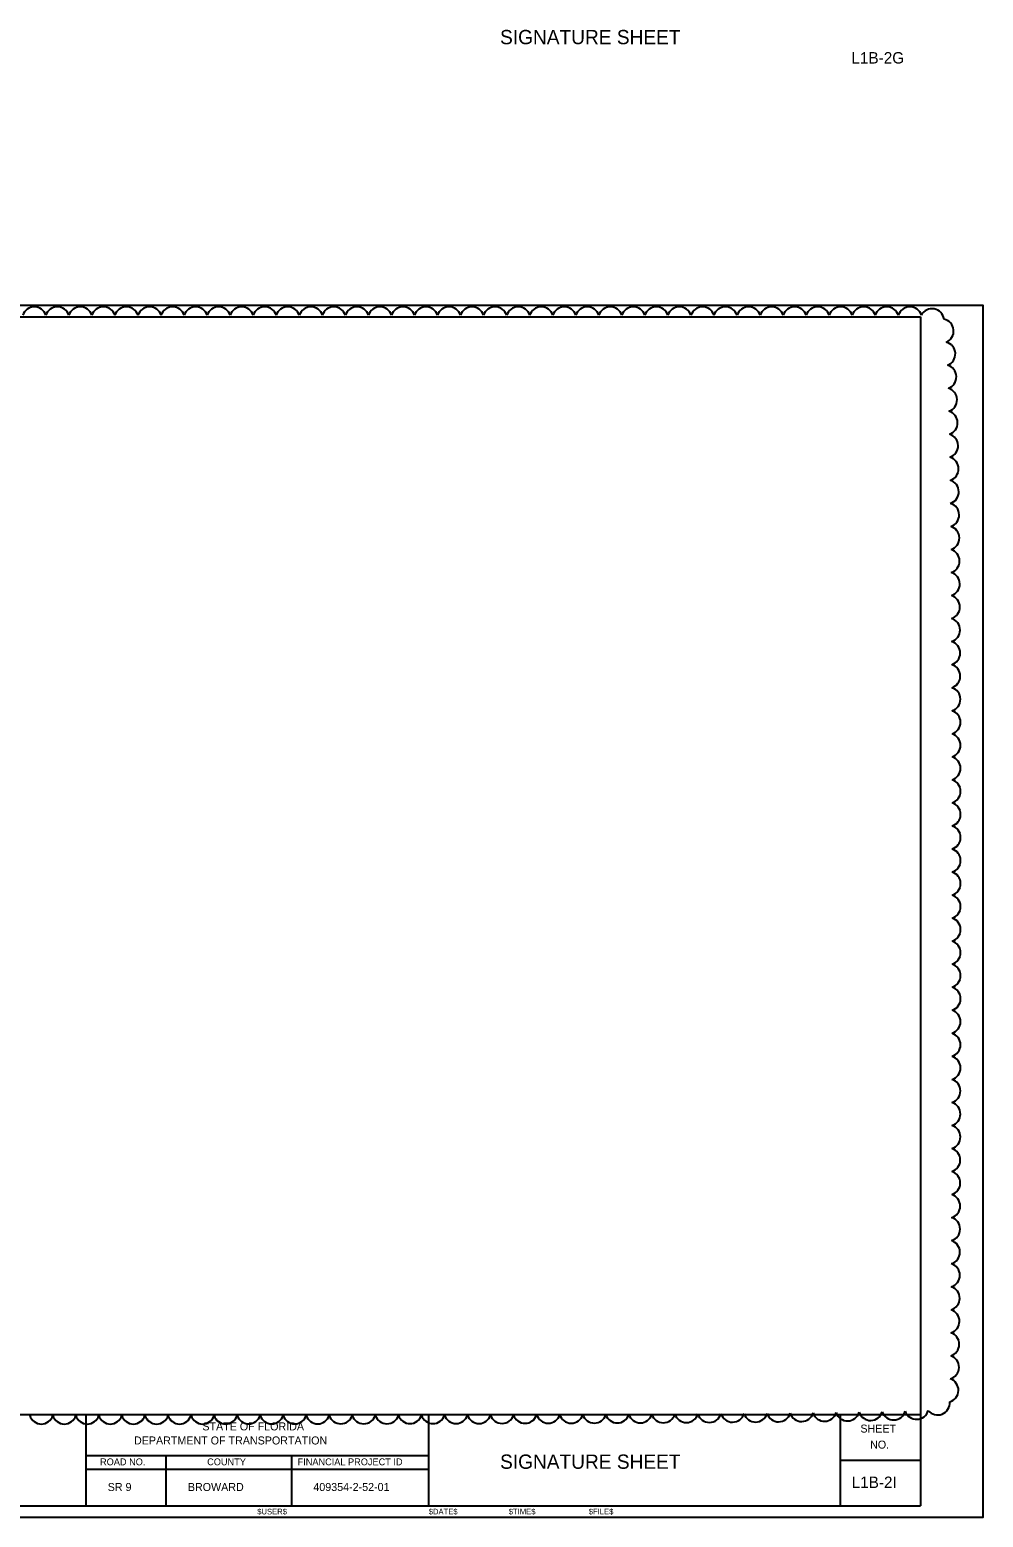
# Model space of a CAD drawing. Extents: x -811.2 to -755.6, y -2295.2 to -2235.1.
# Drawn here: x -775.75 to -767.41, y -2282.95 to -2269.93 of the extents above; entities that cross this region are included whole.
import ezdxf

# ---------------------------------------------------------------- set-up
doc = ezdxf.new("R2010")
doc.units = 0
for name, color, linetype in [('Cloud_dp', 7, 'Continuous'), ('PlotBorder_dp', 7, 'Continuous'), ('SheetBorder_dp', 7, 'Continuous'), ('SheetLines_dp', 7, 'Continuous'), ('TextMinor', 7, 'Continuous'), ('TextMisc', 7, 'Continuous'), ('TextShtNo', 7, 'Continuous')]:
    doc.layers.add(name, color=color, linetype=linetype)

msp = doc.modelspace()

# ---------------------------------------------------------------- linework, layer by layer
at = {"layer": 'Cloud_dp'}
for centre, start, end in [((-775.707, -2272.463), 17.5, 162.5), ((-775.505, -2272.463), 17.5, 162.5), ((-775.304, -2272.463), 17.5, 162.5), ((-775.102, -2272.463), 17.5, 162.5), ((-774.901, -2272.463), 17.5, 162.5), ((-774.699, -2272.463), 17.5, 162.5), ((-774.498, -2272.463), 17.5, 162.5), ((-774.296, -2272.463), 17.5, 162.5), ((-774.095, -2272.463), 17.5, 162.5), ((-773.893, -2272.463), 17.5, 162.5), ((-773.691, -2272.463), 17.5, 162.5), ((-773.49, -2272.463), 17.5, 162.5), ((-773.288, -2272.463), 17.5, 162.5), ((-773.087, -2272.463), 17.5, 162.5), ((-772.885, -2272.463), 17.5, 162.5), ((-772.684, -2272.463), 17.5, 162.5), ((-772.482, -2272.463), 17.5, 162.5), ((-772.281, -2272.463), 17.5, 162.5), ((-772.079, -2272.463), 17.5, 162.5), ((-771.878, -2272.463), 17.5, 162.5), ((-771.676, -2272.463), 17.5, 162.5), ((-771.474, -2272.463), 17.5, 162.5), ((-771.273, -2272.463), 17.5, 162.5), ((-771.071, -2272.463), 17.5, 162.5), ((-770.87, -2272.463), 17.5, 162.5), ((-770.668, -2272.463), 17.5, 162.5), ((-770.467, -2272.463), 17.5, 162.5), ((-770.265, -2272.463), 17.5, 162.5), ((-770.064, -2272.463), 17.5, 162.5), ((-769.862, -2272.463), 17.5, 162.5), ((-769.661, -2272.463), 17.5, 162.5), ((-769.459, -2272.463), 17.5, 162.5), ((-769.257, -2272.463), 17.5, 162.5), ((-769.056, -2272.463), 17.5, 162.5), ((-768.854, -2272.463), 17.5, 162.5), ((-768.653, -2272.463), 17.5, 162.5), ((-768.451, -2272.463), 17.5, 162.5), ((-768.25, -2272.463), 17.5, 162.5), ((-768.048, -2272.463), 17.5, 162.5), ((-767.854, -2272.48), 7.7061, 152.7061), ((-767.771, -2272.569), 293.1451, 78.1451), ((-767.756, -2272.769), 290.3535, 75.3535), ((-767.747, -2272.97), 289.5186, 74.5186), ((-767.741, -2273.171), 289.0656, 74.0656), ((-767.736, -2273.372), 288.7699, 73.7699), ((-767.732, -2273.573), 288.5573, 73.5573), ((-767.728, -2273.775), 288.3949, 73.3949), ((-767.726, -2273.976), 288.2656, 73.2656), ((-767.723, -2274.178), 288.1595, 73.1595), ((-767.721, -2274.379), 288.0704, 73.0704), ((-767.719, -2274.581), 287.9942, 72.9942), ((-767.717, -2274.782), 287.928, 72.928), ((-767.716, -2274.984), 287.8698, 72.8698), ((-767.715, -2275.185), 287.8182, 72.8182), ((-767.714, -2275.387), 287.772, 72.772), ((-767.713, -2275.588), 287.7302, 72.7302), ((-767.712, -2275.79), 287.6923, 72.6923), ((-767.711, -2275.991), 287.6577, 72.6577), ((-767.711, -2276.193), 287.6259, 72.6259), ((-767.711, -2276.394), 287.5965, 72.5965), ((-767.71, -2276.596), 287.5693, 72.5693), ((-767.71, -2276.798), 287.544, 72.544), ((-767.71, -2276.999), 287.5204, 72.5204), ((-767.71, -2277.201), 287.5008, 72.5008), ((-767.71, -2277.402), 287.4924, 72.4924), ((-767.71, -2277.604), 287.4849, 72.4849), ((-767.71, -2277.805), 287.4769, 72.4769), ((-767.71, -2278.007), 287.4682, 72.4682), ((-767.71, -2278.208), 287.4589, 72.4589), ((-767.71, -2278.41), 287.4488, 72.4488), ((-767.711, -2278.611), 287.4378, 72.4378), ((-767.711, -2278.813), 287.4258, 72.4258), ((-767.711, -2279.015), 287.4126, 72.4126), ((-767.712, -2279.216), 287.398, 72.398), ((-767.712, -2279.418), 287.3817, 72.3817), ((-767.712, -2279.619), 287.3633, 72.3633), ((-767.713, -2279.821), 287.3425, 72.3425), ((-767.713, -2280.022), 287.3185, 72.3185), ((-767.714, -2280.224), 287.2905, 72.2905), ((-767.715, -2280.425), 287.2573, 72.2573), ((-767.716, -2280.627), 287.217, 72.217), ((-767.717, -2280.828), 287.1666, 72.1666), ((-767.718, -2281.03), 287.101, 72.101), ((-767.72, -2281.231), 287.0106, 72.0106), ((-767.722, -2281.433), 286.8744, 71.8744), ((-767.724, -2281.634), 286.6317, 71.6317), ((-767.729, -2281.835), 285.9387, 70.9387), ((-767.805, -2281.945), 219.2472, 4.2472), ((-775.646, -2282.024), 197.4989, 342.4989), ((-775.445, -2282.024), 197.5044, 342.5044), ((-775.243, -2282.024), 197.5105, 342.5105), ((-775.042, -2282.024), 197.5167, 342.5167), ((-774.84, -2282.024), 197.5233, 342.5233), ((-774.638, -2282.024), 197.5301, 342.5301), ((-774.437, -2282.024), 197.5372, 342.5372), ((-774.235, -2282.024), 197.5447, 342.5447), ((-774.034, -2282.024), 197.5525, 342.5525), ((-773.832, -2282.023), 197.5607, 342.5607), ((-773.631, -2282.023), 197.5693, 342.5693), ((-773.429, -2282.023), 197.5784, 342.5784), ((-773.228, -2282.023), 197.5879, 342.5879), ((-773.026, -2282.022), 197.598, 342.598), ((-772.825, -2282.022), 197.6087, 342.6087), ((-772.623, -2282.022), 197.62, 342.62), ((-772.421, -2282.021), 197.6321, 342.6321), ((-772.22, -2282.021), 197.6449, 342.6449), ((-772.018, -2282.02), 197.6587, 342.6587), ((-771.817, -2282.02), 197.6734, 342.6734), ((-771.615, -2282.019), 197.6893, 342.6893), ((-771.414, -2282.018), 197.7064, 342.7064), ((-771.212, -2282.017), 197.725, 342.725), ((-771.011, -2282.017), 197.7453, 342.7453), ((-770.809, -2282.016), 197.7675, 342.7675), ((-770.608, -2282.015), 197.792, 342.792), ((-770.406, -2282.014), 197.8192, 342.8192), ((-770.205, -2282.013), 197.8496, 342.8496), ((-770.003, -2282.011), 197.8839, 342.8839), ((-769.802, -2282.01), 197.9231, 342.9231), ((-769.6, -2282.008), 197.9684, 342.9684), ((-769.398, -2282.007), 198.0216, 343.0216), ((-769.197, -2282.005), 198.0853, 343.0853), ((-768.995, -2282.002), 198.1633, 343.1633), ((-768.794, -2282), 198.2623, 343.2623), ((-768.593, -2281.997), 198.3936, 343.3936), ((-768.391, -2281.993), 198.5799, 343.5799), ((-768.19, -2281.989), 198.8753, 343.8753), ((-767.989, -2281.983), 199.4643, 344.4643)]:
    msp.add_arc(centre, 0.106, start, end, dxfattribs=at)
at = {"layer": 'PlotBorder_dp'}
msp.add_lwpolyline([(-783.906, -2282.946), (-767.406, -2282.946), (-767.406, -2272.346), (-783.906, -2272.346)], close=True, dxfattribs=at)
at = {"layer": 'SheetBorder_dp'}
for p, q in [((-783.356, -2272.446), (-767.956, -2272.446)), ((-767.956, -2272.446), (-767.956, -2282.846)), ((-783.356, -2282.046), (-767.956, -2282.046)), ((-783.356, -2282.846), (-767.956, -2282.846))]:
    msp.add_line(p, q, dxfattribs=at)
at = {"layer": 'SheetLines_dp'}
for p, q in [((-775.256, -2282.046), (-775.256, -2282.846)), ((-772.256, -2282.846), (-772.256, -2282.046)), ((-768.656, -2282.846), (-768.656, -2282.046)), ((-775.256, -2282.406), (-772.256, -2282.406)), ((-774.556, -2282.406), (-774.556, -2282.846)), ((-773.456, -2282.406), (-773.456, -2282.846)), ((-768.656, -2282.446), (-767.956, -2282.446)), ((-775.256, -2282.526), (-772.256, -2282.526))]:
    msp.add_line(p, q, dxfattribs=at)

# ---------------------------------------------------------------- texts
at = {"layer": 'TextMinor'}
msp.add_text('$USER$', height=0.05, dxfattribs=at).set_placement((-773.757, -2282.921))
for s, p in [('$DATE$', (-772.257, -2282.921)), ('$TIME$', (-771.557, -2282.921)), ('$FILE$', (-770.857, -2282.921))]:
    msp.add_text(s, height=0.05, rotation=360, dxfattribs=at).set_placement(p)
at = {"layer": 'TextMisc'}
for s, height, p in [('       SIGNATURE SHEET         ', 0.125, (-771.958, -2270.06)), ('STATE OF FLORIDA', 0.07, (-774.237, -2282.186)), ('DEPARTMENT OF TRANSPORTATION', 0.07, (-774.835, -2282.309)), ('ROAD NO.', 0.06, (-775.132, -2282.491)), ('COUNTY', 0.06, (-774.195, -2282.491)), ('FINANCIAL PROJECT ID', 0.06, (-773.404, -2282.491)), ('       SIGNATURE SHEET         ', 0.125, (-771.958, -2282.522)), (' SR 9  ', 0.07, (-775.091, -2282.716)), ('  BROWARD   ', 0.07, (-774.416, -2282.716)), ('409354-2-52-01', 0.07, (-773.266, -2282.716))]:
    msp.add_text(s, height=height, dxfattribs=at).set_placement(p)
for s, p in [('SHEET', (-768.481, -2282.205)), ('NO.', (-768.396, -2282.345))]:
    msp.add_text(s, height=0.07, rotation=359.8607, dxfattribs=at).set_placement(p)
at = {"layer": 'TextShtNo'}
for s, p in [('L1B-2G ', (-768.559, -2270.229)), ('L1B-2I ', (-768.557, -2282.69))]:
    msp.add_text(s, height=0.1, dxfattribs=at).set_placement(p)

doc.saveas('drawing.dxf')
